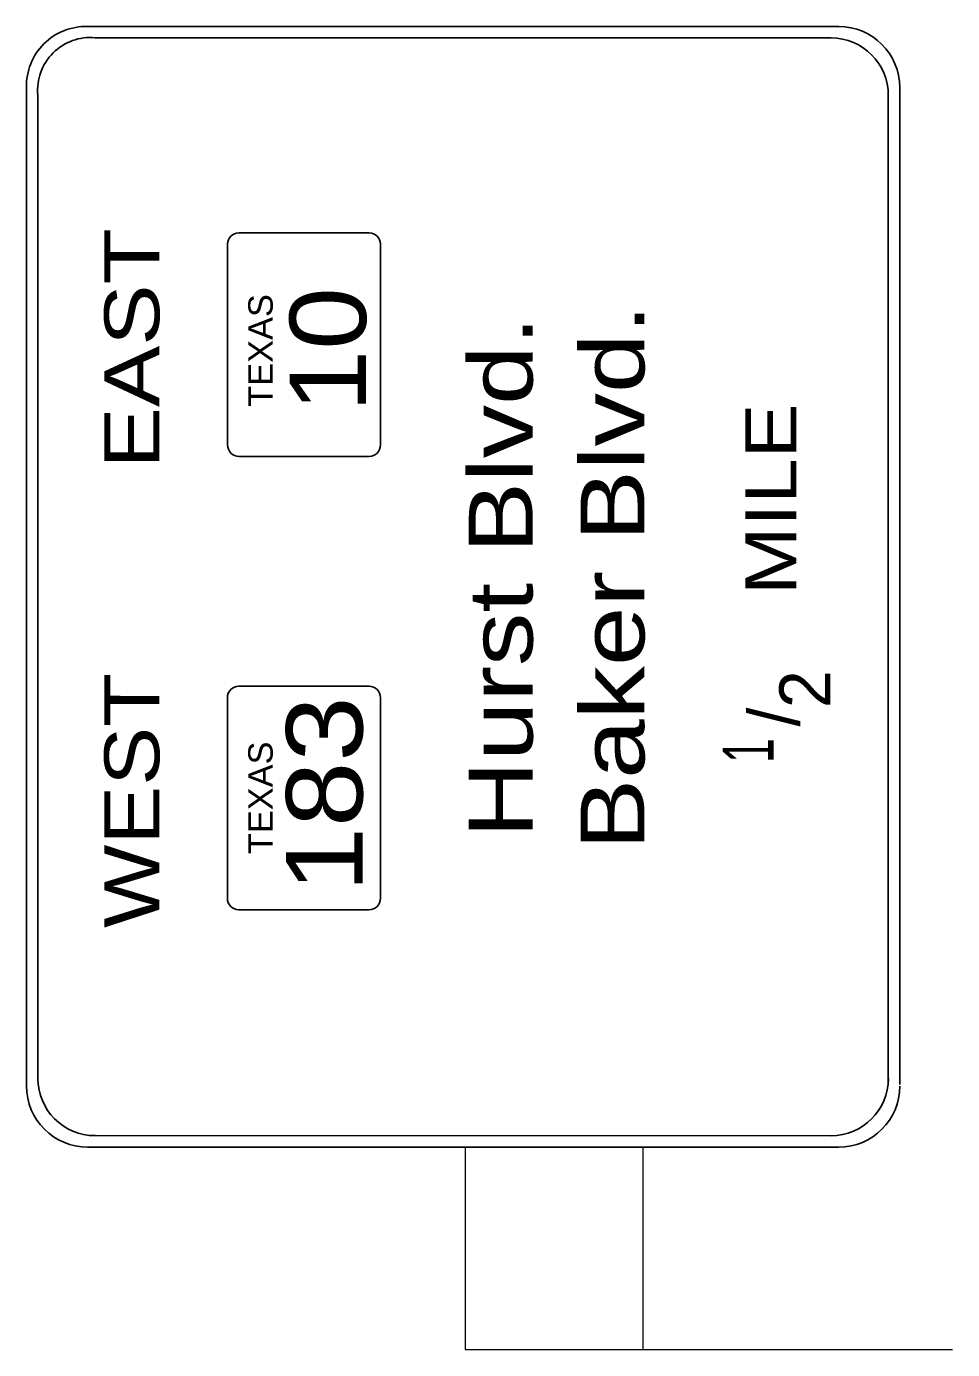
# Model space of a CAD drawing. Extents: x 2363427 to 2368559, y 6957299 to 6980140.
# Drawn here: x 2368331.9 to 2368559.2, y 6970902.9 to 6971227.6 of the extents above; entities that cross this region are included whole.
import ezdxf
from ezdxf.enums import TextEntityAlignment as Align

# ---------------------------------------------------------------- set-up
doc = ezdxf.new("R2010")
doc.units = 0
doc.header["$LTSCALE"] = 5.6
doc.layers.add('48', color=7, linetype='Continuous', lineweight=25)
doc.layers.add('61', color=7, linetype='Continuous', lineweight=25)

msp = doc.modelspace()

# ---------------------------------------------------------------- linework, layer by layer
at = {"layer": '48'}
for p, q in [((2368531.255, 6971227.628), (2368346.935, 6971227.628)), ((2368529.379, 6971224.823), (2368348.803, 6971224.822)), ((2368331.932, 6970967.614), (2368331.932, 6971213.514)), ((2368546.241, 6971212.626), (2368546.256, 6970967.966)), ((2368334.729, 6970969.493), (2368334.714, 6971210.806)), ((2368543.428, 6971210.752), (2368543.435, 6970967.965)), ((2368416.012, 6971176.996), (2368384.068, 6971176.996)), ((2368381.263, 6971174.176), (2368381.27, 6971124.936)), ((2368418.824, 6971124.943), (2368418.817, 6971174.176)), ((2368384.067, 6971122.123), (2368416.004, 6971122.123)), ((2368415.997, 6971065.729), (2368384.068, 6971065.728)), ((2368381.256, 6971062.916), (2368381.248, 6971013.684)), ((2368418.81, 6971013.684), (2368418.81, 6971062.908)), ((2368384.06, 6971010.87), (2368415.99, 6971010.87)), ((2368348.791, 6970955.429), (2368529.388, 6970955.418)), ((2368346.932, 6970952.613), (2368531.255, 6970952.612))]:
    msp.add_line(p, q, dxfattribs=at)
for centre, radius, start, end in [((2368346.549, 6971213.012), 14.621, 88.49246, 181.50574), ((2368531.252, 6971212.628), 15.001, 359.9991, 89.9991), ((2368347.604, 6971211.979), 12.944, 84.80239, 185.19581), ((2368529.377, 6971210.753), 14.063, 359.9991, 89.9991), ((2368384.075, 6971174.178), 2.813, 89.99727, 179.99727), ((2368416.008, 6971174.177), 2.813, 359.99727, 89.99727), ((2368384.073, 6971124.938), 2.813, 179.99727, 269.99727), ((2368416.006, 6971124.937), 2.813, 269.99727, 359.99727), ((2368384.061, 6971062.918), 2.813, 89.99617, 179.99617), ((2368415.993, 6971062.916), 2.813, 359.99617, 89.99617), ((2368384.057, 6971013.679), 2.813, 179.99617, 269.99617), ((2368415.99, 6971013.676), 2.813, 269.99617, 359.99617), ((2368348.791, 6970969.493), 14.063, 179.99852, 269.99852), ((2368529.383, 6970969.483), 14.063, 269.99852, 359.99852), ((2368346.932, 6970967.614), 15.001, 179.99852, 269.99852), ((2368531.258, 6970967.607), 15.001, 269.99852, 359.99852)]:
    msp.add_arc(centre, radius, start, end, dxfattribs=at)
at = {"layer": '61', "lineweight": 13}
for p, q in [((2368439.57, 6970952.612), (2368439.57, 6970902.939)), ((2368483.163, 6970952.612), (2368483.163, 6970902.939)), ((2368439.57, 6970902.939), (2368559.197, 6970902.939))]:
    msp.add_line(p, q, dxfattribs=at)

# ---------------------------------------------------------------- texts
at = {"layer": '48'}
for s, height, rotation, width, p in [('EAST', 13.5, 89.996, 1.25, (2368364.538, 6971148.648)), ('Hurst Blvd.', 15.68, 90.002, 1.25, (2368456.151, 6971092.529)), ('Baker Blvd.', 15.68, 90.002, 1.25, (2368483.588, 6971092.528)), ('MILE', 12.54, 90, 1.2, (2368520.854, 6971111.612)), ('WEST', 13.5, 89.996, 1.2, (2368364.538, 6971037.691)), ('1', 12.54, 90, 0.65, (2368515.306, 6971049.912))]:
    msp.add_text(s, height=height, rotation=rotation, dxfattribs=dict(at, width=width)).set_placement(p, align=Align.CENTER)
for s, height, rotation, width, p in [('TEXAS', 6, 89.997, 1.05, (2368392.362, 6971134.313)), ('10', 18.75, 89.997, 1.1, (2368415.26, 6971132.97)), ('183', 18.75, 89.996, 1.15, (2368414.399, 6971015.132)), ('TEXAS', 6, 89.996, 1.05, (2368392.355, 6971024.522))]:
    msp.add_text(s, height=height, rotation=rotation, dxfattribs=dict(at, width=width)).set_placement(p)
for s, p in [('2', (2368529.234, 6971064.997)), ('/', (2368521.682, 6971058.157))]:
    msp.add_text(s, height=12.54, rotation=90, dxfattribs=at).set_placement(p, align=Align.CENTER)

doc.saveas('drawing.dxf')
